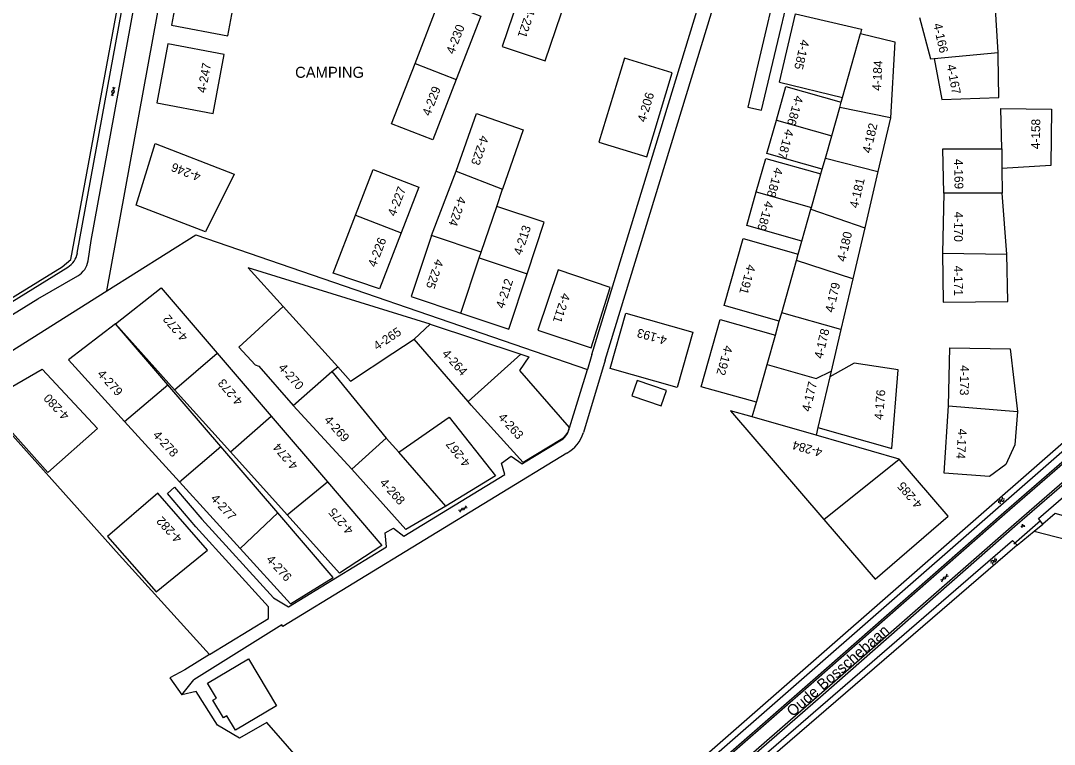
# Model space of a CAD drawing. Extents: x 134297 to 137000, y 403500 to 406000.
# Drawn here: x 136037.3 to 136271.5, y 405083.9 to 405247.8 of the extents above; entities that cross this region are included whole.
import ezdxf

# ---------------------------------------------------------------- set-up
doc = ezdxf.new("R2010")
doc.units = 0
for name, color, linetype in [('gg-afsc-hekwerk', 7, 'Continuous'), ('gg-anno-openbare ruimte label', 7, 'Continuous'), ('gg-bbg-gedigitaliseerde bijgebouw', 7, 'Continuous'), ('gg-knt-bronhoudergrens', 7, 'Continuous'), ('gg-knt-verharding', 7, 'Continuous'), ('gg-kntw-bovenkant insteek waterloop', 7, 'Continuous'), ('gg-kwrk-duiker nz buis', 7, 'Continuous'), ('gt-afsc-standplaatsafbakening', 7, 'Continuous'), ('gt-anno-naam bijzondere bebouwing', 7, 'Continuous'), ('gt-anno-standplaatsnummer', 7, 'Continuous'), ('gt-grn-groengrens', 7, 'Continuous'), ('gt-grn-vlakafsluiter', 7, 'Continuous'), ('gt-symb-gesloten verharding', 7, 'Continuous'), ('gt-symb-groenvak', 7, 'Continuous'), ('gt-symb-watersymbool', 7, 'Continuous')]:
    doc.layers.add(name, color=color, linetype=linetype)

# ---------------------------------------------------------------- blocks, each defined once
blk = doc.blocks.new('gt0-GESVH1')
at = {"layer": 'gt-symb-gesloten verharding'}
for p, q in [((-0.99, -0.26), (0.01, 0.24)), ((0.01, -0.26), (-0.99, 0.24)), ((0.01, 0.24), (1.01, -0.26)), ((1.01, 0.24), (0.01, -0.26))]:
    blk.add_line(p, q, dxfattribs=at)
blk = doc.blocks.new('gt0-WA')
at = {"layer": 'gt-symb-watersymbool'}
for centre, start, end in [((-0.32, 0.02), 28.0725, 151.9275), ((0.43, 0.42), 208.0725, 331.9275), ((-0.32, -0.43), 28.0725, 151.9275), ((0.43, -0.03), 208.0725, 331.9275)]:
    blk.add_arc(centre, 0.425, start, end, dxfattribs=at)
blk = doc.blocks.new('gt0-GRVAK')
at = {"layer": 'gt-symb-groenvak'}
for p, q in [((-0.11, 0.19), (-0.23, 0.24)), ((-0.18, 0.15), (0.09, 0.15)), ((-0.09, 0.21), (-0.16, 0.32)), ((-0.05, 0.21), (-0.05, 0.39)), ((0, 0.21), (0.06, 0.32)), ((0.01, 0.19), (0.13, 0.24)), ((0.26, -0.05), (0.2, 0.06)), ((0.3, -0.05), (0.3, 0.13)), ((0.35, -0.05), (0.41, 0.06)), ((-0.24, -0.23), (-0.36, -0.18)), ((-0.32, -0.26), (-0.05, -0.26)), ((-0.23, -0.21), (-0.29, -0.09)), ((-0.18, -0.2), (-0.18, -0.02)), ((-0.14, -0.21), (-0.07, -0.09)), ((-0.12, -0.23), (0, -0.18)), ((0.24, -0.07), (0.12, -0.02)), ((0.17, -0.11), (0.44, -0.11)), ((0.37, -0.07), (0.49, -0.02))]:
    blk.add_line(p, q, dxfattribs=at)

msp = doc.modelspace()

# ---------------------------------------------------------------- linework, layer by layer
at = {"layer": 'gg-afsc-hekwerk'}
msp.add_line((136020.02, 405163.47), (136056.85, 405186.66), dxfattribs=at)
for points in [[(136048.7, 405193.79), (136066.79, 405291.22), (136069.9, 405308.54)], [(136056.85, 405186.66), (136073.48, 405277.45), (136076.73, 405291.59), (136076.95, 405292.86), (136077.8, 405300.05)], [(136000, 405163.36), (136046.75, 405192.1), (136048.7, 405193.79)]]:
    msp.add_lwpolyline(points, dxfattribs=at)
at = {"layer": 'gg-bbg-gedigitaliseerde bijgebouw'}
for points in [[(136175.82, 405162.9), (136182.48, 405160.62), (136183.67, 405164.1), (136177, 405166.37), (136175.82, 405162.9)], [(136079.66, 405097.83), (136088.96, 405103.33), (136095.29, 405092.65), (136085.99, 405087.14), (136084.06, 405090.4), (136083.27, 405089.94), (136080.9, 405093.96), (136081.68, 405094.42), (136079.66, 405097.83)]]:
    msp.add_lwpolyline(points, dxfattribs=at)
at = {"layer": 'gg-knt-bronhoudergrens'}
for points in [[(136080.16, 405104.26), (136059.64, 405126.84), (136027.18, 405163.11), (136022.14, 405160.42)], [(136266.95, 405132.2), (136317.46, 405119.24), (136319.18, 405122.94), (136271.73, 405136.25)], [(136131.76, 405035.76), (136136.32, 405039.45), (136093.14, 405088.9), (136086.95, 405085.33), (136081.95, 405088.26), (136077.1, 405095.88), (136073.85, 405095.17)]]:
    msp.add_lwpolyline(points, dxfattribs=at)
at = {"layer": 'gg-knt-verharding'}
for p, q in [((136050.18, 405195.18), (136065.1, 405276.43)), ((136169.8, 405170.95), (136164.85, 405154.56)), ((136166.79, 405172.24), (136165.74, 405168.81)), ((136161.71, 405155.63), (136165.74, 405168.81)), ((136161.62, 405155.33), (136161.71, 405155.63)), ((136151.28, 405147.68), (136159.5, 405152.66)), ((136073.85, 405095.17), (136076.57, 405098.53))]:
    msp.add_line(p, q, dxfattribs=at)
for points in [[(136052.61, 405193.44), (136053.3, 405198.08), (136067.59, 405275.93), (136069.31, 405284.15)], [(136211.51, 405268.47), (136202.08, 405228.24), (136205.21, 405227.55), (136214.82, 405267.99), (136218.12, 405274.71), (136268.42, 405281.76), (136271.54, 405265.3)], [(136166.79, 405172.24), (136195.64, 405266.6), (136195.53, 405267.72), (136195.08, 405268.98), (136194.4, 405270.34), (136193.55, 405271.37)], [(136169.8, 405170.95), (136199.52, 405268.17), (136202.56, 405272.54)], [(135946.3, 405129.5), (135950.53, 405131.78), (136000, 405162.38), (136048.03, 405192.03)], [(135947.4, 405127.11), (135951.69, 405129.47), (136041.25, 405184.86), (136050.31, 405190.07)], [(136315.88, 405184.77), (136260.13, 405136.41), (136216.79, 405098.39), (136189.84, 405074.86), (136173.44, 405060.47), (136146.26, 405036.51), (136141.6, 405032.44)], [(136315.91, 405184.29), (136311.27, 405180.23), (136260.36, 405136.04), (136217.06, 405098.08), (136190.12, 405074.57), (136173.71, 405060.18)], [(136144.4, 405029.71), (136148.88, 405033.62), (136176.01, 405057.56), (136192.38, 405071.92), (136219.13, 405095.26), (136262.58, 405133.36), (136279.35, 405147.86), (136318.44, 405181.61)], [(136318.01, 405181.73), (136279.08, 405148.18), (136262.33, 405133.67), (136218.89, 405095.62), (136192.13, 405072.26), (136175.76, 405057.87)], [(136080.16, 405104.26), (136093.51, 405112.45), (136093.48, 405115.11), (136077.05, 405133.23), (136070.59, 405140.78), (136072.18, 405142.18), (136078.38, 405134.93), (136094.6, 405117.09), (136098.03, 405115.08), (136120.26, 405128.7), (136119.93, 405131.82), (136121.8, 405132.93), (136124.19, 405131.09), (136147.02, 405145.08), (136146.26, 405147.64), (136148.51, 405149.21), (136150.94, 405147.47), (136151.28, 405147.68)], [(136161.1, 405149.9), (136096.74, 405110.65), (136096.54, 405110.98), (136076.57, 405098.53)], [(136080.16, 405104.26), (136074.55, 405100.82), (136071.15, 405098.98), (136073.85, 405095.17)]]:
    msp.add_lwpolyline(points, dxfattribs=at)
for centre, radius, start, end in [((136045.56, 405196.03), 4.7, 301.6937, 349.6029), ((136047.97, 405194.13), 4.69, 299.894, 351.5828), ((136157.36, 405156.54), 4.43, 298.9337, 344.1511), ((136157.42, 405156.7), 7.73, 298.4355, 343.9365)]:
    msp.add_arc(centre, radius, start, end, dxfattribs=at)
at = {"layer": 'gg-kntw-bovenkant insteek waterloop'}
for p, q in [((136140.14, 405033.86), (136314.81, 405186.55)), ((136271.73, 405136.25), (136268.93, 405133.83))]:
    msp.add_line(p, q, dxfattribs=at)
for points in [[(136314, 405187.62), (136139.17, 405034.79), (136135.44, 405031.58)], [(136268.93, 405133.83), (136267.96, 405135.1), (136319.95, 405180.1)], [(136193.54, 405068.31), (136192.53, 405069.29), (136198.24, 405074.66), (136204.03, 405079.94), (136262.1, 405130.11), (136263.1, 405129.04)], [(136263.1, 405129.04), (136205.04, 405078.96), (136199.25, 405073.68), (136193.54, 405068.31)]]:
    msp.add_lwpolyline(points, dxfattribs=at)
at = {"layer": 'gg-kwrk-duiker nz buis'}
msp.add_line((136262.37, 405129.39), (136268.42, 405134.64), dxfattribs=at)
at = {"layer": 'gt-afsc-standplaatsafbakening'}
for p, q in [((136258.78, 405240.65), (136258.12, 405251.76)), ((136223.55, 405230.48), (136227.64, 405244.92)), ((136244.31, 405239.29), (136258.78, 405240.65)), ((136258.79, 405239.88), (136258.78, 405240.65)), ((136121.4, 405224.46), (136126.71, 405238.17)), ((136126.71, 405238.17), (136136.04, 405234.55)), ((136209.27, 405233.9), (136223.55, 405230.48)), ((136222.91, 405228.21), (136223.25, 405229.39)), ((136223.25, 405229.39), (136223.55, 405230.48)), ((136136.05, 405213.75), (136140.59, 405226.82)), ((136140.59, 405226.82), (136151.19, 405223.14)), ((136221.1, 405221.79), (136222.91, 405228.21)), ((136234.42, 405225.84), (136222.91, 405228.21)), ((136259.67, 405218.85), (136259.4, 405227.93)), ((136208.59, 405225.33), (136221.1, 405221.79)), ((136234.42, 405225.84), (136231.57, 405213.66)), ((136151.19, 405223.14), (136146.54, 405209.69)), ((136219.66, 405216.7), (136221.1, 405221.79)), ((136246.27, 405218.81), (136259.67, 405218.85)), ((136246.47, 405208.76), (136246.27, 405218.81)), ((136259.67, 405218.85), (136259.68, 405214.36)), ((136218.95, 405214.2), (136219.66, 405216.7)), ((136219.66, 405216.7), (136231.57, 405213.66)), ((136130.41, 405199.19), (136136.05, 405213.75)), ((136136.05, 405213.75), (136146.54, 405209.69)), ((136216.5, 405205.52), (136218.65, 405213.12)), ((136218.65, 405213.12), (136218.95, 405214.2)), ((136231.57, 405213.66), (136228.59, 405200.94)), ((136259.68, 405214.36), (136259.7, 405208.8)), ((136145.2, 405205.76), (136146.54, 405209.69)), ((136203.99, 405209.05), (136216.5, 405205.52)), ((136246.47, 405208.76), (136246.24, 405195.19)), ((136259.7, 405208.8), (136246.47, 405208.76)), ((136260.79, 405194.95), (136259.7, 405208.8)), ((136141.7, 405195.44), (136145.2, 405205.76)), ((136216.4, 405205.18), (136216.5, 405205.52)), ((136108.14, 405190.68), (136113.22, 405203.81)), ((136113.22, 405203.81), (136123.55, 405199.82)), ((136214.35, 405197.92), (136216.4, 405205.18)), ((136216.4, 405205.18), (136228.59, 405200.94)), ((136228.59, 405200.94), (136225.89, 405189.41)), ((136141.7, 405195.44), (136130.41, 405199.19)), ((136213.52, 405194.96), (136214.35, 405197.92)), ((136137.1, 405181.61), (136141.25, 405194.11)), ((136141.25, 405194.11), (136141.7, 405195.44)), ((136141.25, 405194.11), (136152.12, 405190.5)), ((136213.1, 405193.5), (136213.52, 405194.96)), ((136246.24, 405195.19), (136260.79, 405194.95)), ((136130.12, 405179.08), (136088.87, 405191.86)), ((136088.87, 405191.86), (136096.8, 405183.09)), ((136209.77, 405181.68), (136213.1, 405193.5)), ((136225.89, 405189.41), (136213.1, 405193.5)), ((136225.89, 405189.41), (136223.2, 405177.92)), ((136096.8, 405183.09), (136109.18, 405169.42)), ((136208.33, 405176.61), (136209.22, 405179.77)), ((136209.22, 405179.77), (136209.77, 405181.68)), ((136223.2, 405177.92), (136209.77, 405181.68)), ((136072.22, 405164.27), (136058.82, 405179.18)), ((136070.66, 405165.4), (136058.82, 405179.18)), ((136126.52, 405175.72), (136130.12, 405179.08)), ((136130.12, 405179.08), (136150.66, 405172.34)), ((136223.2, 405177.92), (136220.99, 405168.48)), ((136138.72, 405161.58), (136126.52, 405175.72)), ((136206.46, 405169.97), (136208.33, 405176.61)), ((136072.22, 405164.27), (136081.85, 405172.54)), ((136081.85, 405172.54), (136094.09, 405158.27)), ((136138.72, 405161.58), (136150.66, 405172.34)), ((136099.1, 405160.71), (136107.86, 405168.38)), ((136107.86, 405168.38), (136109.18, 405169.42)), ((136107.86, 405168.38), (136120.17, 405153.29)), ((136204.11, 405161.67), (136206.46, 405169.97)), ((136220.99, 405168.48), (136220.69, 405167.2)), ((136220.69, 405167.2), (136217.99, 405155.68)), ((136060.9, 405157.03), (136070.66, 405165.4)), ((136082.67, 405151.42), (136070.66, 405165.4)), ((136084.86, 405150.2), (136072.22, 405164.27)), ((136203.1, 405158.09), (136204.04, 405161.41)), ((136204.04, 405161.41), (136204.11, 405161.67)), ((136112.34, 405146.27), (136099.1, 405160.71)), ((136198.14, 405159.51), (136219.35, 405134.84)), ((136203.1, 405158.09), (136198.14, 405159.51)), ((136247.59, 405160.59), (136263.16, 405159.36)), ((136060.9, 405157.03), (136073.32, 405143.41)), ((136084.86, 405150.2), (136094.09, 405158.27)), ((136094.09, 405158.27), (136106.88, 405143.36)), ((136123.03, 405150.1), (136134.4, 405158.01)), ((136217.58, 405153.93), (136203.1, 405158.09)), ((136217.99, 405155.68), (136217.58, 405153.93)), ((136236.36, 405148.55), (136217.58, 405153.93)), ((136112.34, 405146.27), (136120.17, 405153.29)), ((136120.17, 405153.29), (136123.03, 405150.1)), ((136073.32, 405143.41), (136082.67, 405151.42)), ((136095.62, 405136.36), (136082.67, 405151.42)), ((136097.69, 405135.93), (136084.86, 405150.2)), ((136133.65, 405137.92), (136123.03, 405150.1)), ((136219.35, 405134.84), (136236.36, 405148.55)), ((136073.32, 405143.41), (136087.11, 405128.28)), ((136097.69, 405135.93), (136106.88, 405143.36)), ((136087.11, 405128.28), (136095.62, 405136.36))]:
    msp.add_line(p, q, dxfattribs=at)
for points in [[(136074.02, 405260.18), (136071.49, 405246.83), (136084.26, 405244.41), (136086.79, 405257.76), (136074.02, 405260.18)], [(136151.3, 405256.29), (136146.46, 405242.01), (136156.17, 405238.72), (136161, 405253), (136151.3, 405256.29)], [(136126.71, 405238.17), (136132.24, 405252.47), (136141.58, 405248.85), (136136.04, 405234.55)], [(136209.27, 405233.9), (136212.91, 405249.42), (136227.87, 405245.91), (136227.64, 405244.92)], [(136240.99, 405248.56), (136243.49, 405239.22), (136244.31, 405239.29)], [(136227.64, 405244.92), (136235.37, 405243.07), (136234.42, 405225.84)], [(136070.69, 405242.6), (136068.16, 405229.25), (136080.93, 405226.83), (136083.46, 405240.18), (136070.69, 405242.6)], [(136174.15, 405239.35), (136168.34, 405220.34), (136179.18, 405217.02), (136184.99, 405236.03), (136174.15, 405239.35)], [(136244.31, 405239.29), (136246.08, 405230), (136258.95, 405230.41), (136258.79, 405239.88)], [(136136.04, 405234.55), (136130.74, 405220.84), (136121.4, 405224.46)], [(136208.59, 405225.33), (136210.74, 405232.93), (136223.25, 405229.39)], [(136259.4, 405227.93), (136270.9, 405227.77), (136270.72, 405215.01), (136259.68, 405214.36)], [(136218.95, 405214.2), (136206.44, 405217.73), (136208.59, 405225.33)], [(136067.78, 405220.02), (136085.7, 405213.09), (136079.22, 405200.05), (136063.52, 405206.04), (136067.78, 405220.02)], [(136203.99, 405209.05), (136206.14, 405216.65), (136218.65, 405213.12)], [(136113.22, 405203.81), (136117.22, 405214.14), (136127.55, 405210.15), (136123.55, 405199.82)], [(136214.35, 405197.92), (136201.84, 405201.46), (136203.99, 405209.05)], [(136152.12, 405190.5), (136155.99, 405202.18), (136145.2, 405205.76)], [(136123.55, 405199.82), (136118.63, 405187.1), (136108.14, 405190.68)], [(136130.41, 405199.19), (136125.82, 405185.36), (136137.1, 405181.61)], [(136209.22, 405179.77), (136196.71, 405183.3), (136201.01, 405198.5), (136213.52, 405194.96)], [(136246.24, 405195.19), (136246.34, 405184.11), (136261.02, 405184.24), (136260.79, 405194.95)], [(136159.09, 405191.4), (136154.55, 405177.74), (136166.61, 405173.74), (136170.88, 405187.4), (136159.09, 405191.4)], [(136137.1, 405181.61), (136147.97, 405178.01), (136152.12, 405190.5)], [(136058.82, 405179.18), (136069.19, 405187.3), (136081.85, 405172.54)], [(136096.8, 405183.09), (136086.78, 405173.93), (136090.46, 405169.9), (136091.28, 405169.61), (136099.1, 405160.71)], [(136186.11, 405164.78), (136170.91, 405169.07), (136174.45, 405181.58), (136189.64, 405177.29), (136186.11, 405164.78)], [(136204.04, 405161.41), (136191.53, 405164.95), (136195.82, 405180.14), (136208.33, 405176.61)], [(136058.82, 405179.18), (136048.15, 405171.01), (136060.9, 405157.03)], [(136109.18, 405169.42), (136112.1, 405166.19), (136121.69, 405172.5), (136126.52, 405175.72)], [(136247.59, 405160.59), (136247.83, 405173.78), (136261.52, 405173.53), (136263.16, 405159.36)], [(136150.66, 405172.34), (136152.51, 405171.74), (136150.33, 405168.62), (136161.64, 405155.7)], [(136217.99, 405155.68), (136234.73, 405150.95), (136236.13, 405168.75), (136226.17, 405170.27), (136220.69, 405167.2)], [(136029.23, 405161.43), (136042.23, 405168.93), (136054.77, 405155.44), (136043.47, 405145.53), (136029.23, 405161.43)], [(136206.46, 405169.97), (136217.58, 405166.77), (136220.99, 405168.48)], [(136161.64, 405155.7), (136161.29, 405154.68), (136160.52, 405153.57), (136159.8, 405153.01), (136151.2, 405147.76), (136139.4, 405160.79), (136138.72, 405161.58)], [(136263.16, 405159.36), (136262.56, 405151.79), (136260.58, 405147.34), (136256.85, 405144.63), (136246.61, 405145.33), (136247.59, 405160.59)], [(136134.4, 405158.01), (136144.92, 405144.73), (136133.65, 405137.92)], [(136219.35, 405134.84), (136230.92, 405121.38), (136247.48, 405135.62), (136236.36, 405148.55)], [(136133.65, 405137.92), (136124.63, 405132.57), (136112.34, 405146.27)], [(136106.88, 405143.36), (136119.18, 405129.01), (136109.55, 405122.74), (136097.69, 405135.93)], [(136057.01, 405131.02), (136068.04, 405118.46), (136079.68, 405127.91), (136068.43, 405140.84), (136057.01, 405131.02)], [(136087.11, 405128.28), (136098.49, 405115.8), (136108.17, 405121.75), (136095.62, 405136.36)]]:
    msp.add_lwpolyline(points, dxfattribs=at)
at = {"layer": 'gt-grn-groengrens'}
for p, q in [((136266.95, 405132.2), (136268.93, 405133.83)), ((136263.1, 405129.04), (136266.95, 405132.2))]:
    msp.add_line(p, q, dxfattribs=at)
at = {"layer": 'gt-grn-vlakafsluiter'}
msp.add_lwpolyline([(136056.85, 405186.66), (136077.03, 405199.37), (136165.74, 405168.81)], dxfattribs=at)

# ---------------------------------------------------------------- block references
at = {"layer": 'gt-symb-gesloten verharding'}
for p, rotation in [((136058.26, 405231.79), 77.99329169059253), ((136137.56, 405137.24), -148.6138752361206), ((136246.65, 405121.59), -138.0000087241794)]:
    msp.add_blockref('gt0-GESVH1', p, dxfattribs=dict(at, rotation=rotation))
at = {"layer": 'gt-symb-groenvak', "rotation": 2.750834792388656}
msp.add_blockref('gt0-GRVAK', (136264.4, 405133.44), dxfattribs=at)
at = {"layer": 'gt-symb-watersymbool'}
for p, rotation in [((136259.48, 405139.1), 54.97512672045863), ((136257.78, 405125.4), 54.9751267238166)]:
    msp.add_blockref('gt0-WA', p, dxfattribs=dict(at, rotation=rotation))

# ---------------------------------------------------------------- texts
at = {"layer": 'gg-anno-openbare ruimte label'}
msp.add_text('Oude Bosschebaan', height=2.5, rotation=41.1, dxfattribs=at).set_placement((136212.24, 405090.05))
at = {"layer": 'gt-anno-naam bijzondere bebouwing'}
msp.add_text('CAMPING', height=2.5, dxfattribs=at).set_placement((136099.53, 405234.9))
at = {"layer": 'gt-anno-standplaatsnummer'}
for s, rotation, p in [('4-221', 251.2869, (136152.11, 405250.88)), ('4-230', 68.8385, (136135.51, 405240.11)), ('4-166', 282.4859, (136244.1, 405247.05)), ('4-185', 256.8034, (136214.14, 405243.7)), ('4-247', 79.2772, (136079.24, 405231.34)), ('4-184', 86.8591, (136232.25, 405231.92)), ('4-167', 280.813, (136247.15, 405237.75)), ('4-229', 68.8385, (136130.09, 405226.1)), ('4-206', 72.9993, (136178.91, 405224.7)), ('4-186', 254.2176, (136212.8, 405231.03)), ('4-182', 76.8191, (136229.95, 405217.71)), ('4-158', 89.193, (136268.27, 405218.74)), ('4-223', 251.2869, (136141.55, 405222.02)), ('4-187', 254.2176, (136210.65, 405223.43)), ('4-246', 158.8385, (136078.34, 405213.26)), ('4-169', 271.1701, (136248.81, 405216.52)), ('4-188', 254.2176, (136208.2, 405214.75)), ('4-227', 68.8385, (136122.25, 405203.38)), ('4-181', 76.8191, (136227.04, 405205.26)), ('4-224', 251.2869, (136136.46, 405208.21)), ('4-189', 254.2176, (136206.05, 405207.15)), ('4-170', 269.0477, (136248.9, 405204.61)), ('4-213', 71.634, (136150.84, 405194.58)), ('4-226', 68.8385, (136117.79, 405191.86)), ('4-180', 76.8191, (136224.2, 405193.13)), ('4-225', 251.2869, (136131.34, 405194.01)), ('4-191', 254.2176, (136201.99, 405192.8)), ('4-171', 270.5084, (136248.77, 405192.35)), ('4-212', 71.634, (136146.82, 405182.5)), ('4-179', 76.8191, (136221.5, 405181.62)), ('4-211', 251.634, (136160.04, 405186.32)), ('4-272', 130.6135, (136075.37, 405176.26)), ('4-265', 33.3364, (136118.08, 405173.11)), ('4-193', 164.2176, (136183.94, 405176.3)), ('4-178', 76.8191, (136219.05, 405171.16)), ('4-264', 312.1516, (136132.67, 405172.31)), ('4-192', 254.2176, (136196.81, 405174.44)), ('4-279', 312.3573, (136054.57, 405167.69)), ('4-270', 311.9056, (136095.6, 405169.12)), ('4-173', 268.9751, (136250.25, 405169.82)), ('4-273', 130.6135, (136087.82, 405161.74)), ('4-177', 76.8191, (136216.24, 405159.17)), ('4-280', 132.8996, (136048.49, 405158.52)), ('4-176', 85.4924, (136232.72, 405157.38)), ('4-263', 312.1516, (136145.39, 405157.9)), ('4-269', 311.9056, (136105.96, 405157.3)), ('4-278', 312.3573, (136067.15, 405153.88)), ('4-174', 266.3094, (136249.76, 405155.47)), ('4-274', 130.6135, (136100.33, 405147.15)), ('4-267', 128.3662, (136139.36, 405147.72)), ('4-284', 164.0003, (136219.14, 405150.89)), ('4-268', 311.9056, (136118.56, 405143.08)), ('4-285', 130.6932, (136241.77, 405138.42)), ('4-277', 312.3573, (136080.26, 405139.51)), ('4-275', 130.6135, (136112.88, 405132.52)), ('4-282', 132.8996, (136074.05, 405130.71)), ('4-276', 312.3573, (136092.85, 405125.7))]:
    msp.add_text(s, height=2, rotation=rotation, dxfattribs=at).set_placement(p)

doc.saveas('drawing.dxf')
